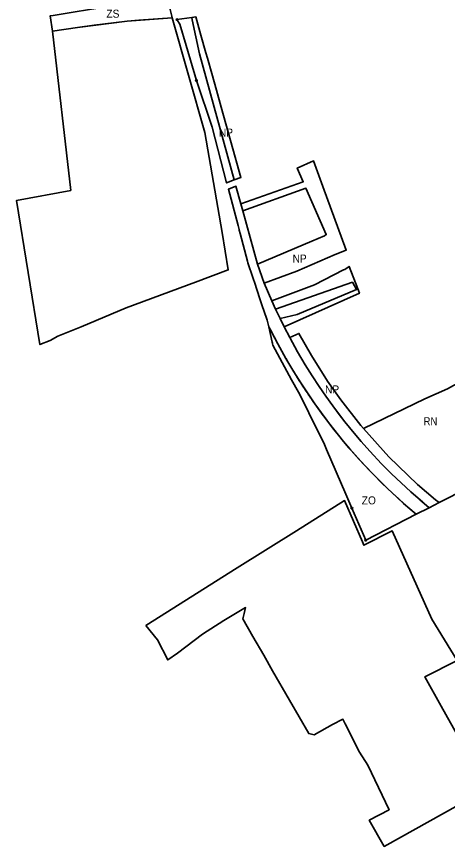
# Model space of a CAD drawing. Extents: x -650276 to -642489, y -1074311 to -1066658.
# Drawn here: x -649386 to -648741, y -1071627 to -1070383 of the extents above; entities that cross this region are included whole.
import ezdxf

# ---------------------------------------------------------------- set-up
doc = ezdxf.new("R2010")
doc.units = 0
doc.header["$LTSCALE"] = 4.8
doc.header["$PDMODE"] = 32
doc.header["$PDSIZE"] = 2.4
for name, color, linetype, lineweight in [('2', 7, 'Continuous', 35), ('24', 7, 'Continuous', 35), ('41', 7, 'Continuous', 35), ('42', 7, 'Continuous', 35), ('48', 7, 'Continuous', 35), ('7', 7, 'Continuous', 35)]:
    doc.layers.add(name, color=color, linetype=linetype, lineweight=lineweight)
doc.layers.add('62', color=7, linetype='Continuous')

msp = doc.modelspace()

# ---------------------------------------------------------------- linework, layer by layer
at = {"layer": '2'}
for points in [[(-649332.2, -1070405.42), (-649294.79, -1070399.65), (-649220.16, -1070390.26), (-649153.11, -1070385.21), (-649104, -1070557), (-649078, -1070707), (-649069, -1070763), (-649118.07, -1070781.42), (-649221.94, -1070820.12), (-649289.37, -1070848.48), (-649324.21, -1070862.51), (-649335.72, -1070868.73), (-649351, -1070875), (-649386, -1070659), (-649305, -1070644)], [(-649192.568, -1071295.954), (-649055.64, -1071209.682), (-648966.9, -1071154.34), (-648894.684, -1071108.668), (-648867.88, -1071170.58), (-648865.61, -1071175.825), (-648823.531, -1071154.018), (-648764.17, -1071286.65), (-648725.85, -1071348.28), (-648774.371, -1071372.773), (-648749.854, -1071416.727), (-648680.709, -1071540.691), (-648835.095, -1071627.059), (-648857.66, -1071587.83), (-648827.998, -1071572.04), (-648859.97, -1071505.55), (-648872.28, -1071485.58), (-648893.65, -1071443.47), (-648897.169, -1071436.535), (-648912.69, -1071444.48), (-648940.23, -1071459.65), (-648948.27, -1071457.92), (-648976.99, -1071408.03), (-649002.42, -1071363.86), (-649015.83, -1071340.58), (-649031.91, -1071312.65), (-649047.3, -1071285.92), (-649045.19, -1071277.86), (-649042.927, -1071269.216), (-649075.6, -1071288.29), (-649107.36, -1071308.9), (-649144.99, -1071337.61), (-649159.64, -1071347.68), (-649175.1, -1071317.29)]]:
    msp.add_lwpolyline(points, close=True, dxfattribs=at)
at = {"layer": '24'}
for points in [[(-649059.951, -1070628.223), (-649112.14, -1070439.152), (-649123.138, -1070388.16), (-649123.385, -1070384.775), (-649145.73, -1070387.91)], [(-649145.73, -1070387.91), (-649141.48, -1070394.84), (-649132.07, -1070426.81), (-649116.56, -1070479.19)], [(-649116.56, -1070479.19), (-649093.2, -1070549.1), (-649071.33, -1070632.6), (-649059.951, -1070628.223)]]:
    msp.add_lwpolyline(points, dxfattribs=at)
msp.add_lwpolyline([(-648976.834, -1070864.527), (-648985.145, -1070848.538), (-648991.386, -1070835.954), (-648998.132, -1070821.723), (-649003.641, -1070809.566), (-649014.888, -1070782.994), (-649025.129, -1070754.377), (-649047.11, -1070674.743), (-649050.081, -1070663.981), (-649057.338, -1070637.689), (-649068.65, -1070642.23), (-649068.65, -1070642.23), (-649054.31, -1070696.44), (-649052.77, -1070702.25), (-649052.44, -1070703.48), (-649051.03, -1070708.74), (-649040.03, -1070750.06), (-649039.38, -1070752.51), (-649039.06, -1070753.72), (-649038.51, -1070755.38), (-649027.74, -1070787.51), (-649027.64, -1070787.8), (-649019.48, -1070812.18), (-649018.48, -1070815.18), (-649011.24, -1070836.79), (-649010.67, -1070838.5), (-649007.885, -1070848.153), (-648994.464, -1070873.974), (-648982.467, -1070895.704), (-648970.712, -1070915.663), (-648960.268, -1070932.429), (-648949.389, -1070949.031), (-648939.232, -1070963.818), (-648918.601, -1070991.969), (-648896.068, -1071020.184), (-648886.874, -1071031.044), (-648874.793, -1071044.773), (-648863.847, -1071056.723), (-648851.175, -1071069.886), (-648838.696, -1071082.562), (-648823.087, -1071097.562), (-648816.379, -1071103.782), (-648806.239, -1071112.938), (-648797, -1071121), (-648790.23, -1071126.818), (-648787.207, -1071129.363), (-648767.824, -1071119.455), (-648771.725, -1071116.233), (-648781.806, -1071107.721), (-648795.407, -1071095.8), (-648824.292, -1071068.677), (-648839.273, -1071053.556), (-648856.883, -1071034.761), (-648869.629, -1071020.411), (-648880.44, -1071007.703), (-648894.164, -1070990.806), (-648902.714, -1070979.812), (-648912.396, -1070966.893), (-648922.92, -1070952.242), (-648932.78, -1070937.887), (-648943.414, -1070921.659), (-648953.605, -1070905.299), (-648965.093, -1070885.794)], close=True, dxfattribs=at)
for p in [(-649145.73, -1070387.91), (-649116.56, -1070479.19)]:
    msp.add_point(p, dxfattribs=at)
at = {"layer": '41'}
msp.add_lwpolyline([(-649159.19, -1070358.82), (-649197.91, -1070361.8), (-649203.4, -1070362.23), (-649220.47, -1070363.94), (-649231.39, -1070365.69), (-649273.57, -1070372.44), (-649304.18, -1070377.35), (-649331.3, -1070381.69), (-649335.79, -1070382.41), (-649332.2, -1070405.42), (-649294.79, -1070399.65), (-649269.769, -1070396.502), (-649220.16, -1070390.26), (-649202.969, -1070388.965), (-649153.11, -1070385.21), (-649153.64, -1070382.9)], close=True, dxfattribs=at)
at = {"layer": '42'}
for p, q in [((-648883.73, -1071120.13), (-648862.97, -1071168.09)), ((-648862.97, -1071168.09), (-648787.207, -1071129.363))]:
    msp.add_line(p, q, dxfattribs=at)
for points in [[(-649002.97, -1070857.609), (-649007.885, -1070848.153), (-649003.1, -1070871.35), (-649002.82, -1070872.69), (-649002.62, -1070873.69), (-649002.15, -1070875.96), (-648974.4, -1070927.77), (-648963.5, -1070946.45), (-648959.92, -1070953.73), (-648948.29, -1070977.37), (-648924.92, -1071024.89), (-648922.98, -1071029.49), (-648921.87, -1071032.04), (-648892.82, -1071099.15), (-648883.73, -1071120.13)], [(-648994.42, -1070874.053), (-648994.464, -1070873.974), (-648994.52, -1070873.867)], [(-648982.403, -1070895.812), (-648982.467, -1070895.704), (-648982.524, -1070895.601)], [(-648970.64, -1070915.778), (-648970.712, -1070915.663), (-648970.771, -1070915.564)], [(-648960.194, -1070932.542), (-648960.268, -1070932.429), (-648960.34, -1070932.313)], [(-648949.345, -1070949.096), (-648949.389, -1070949.031), (-648949.428, -1070948.972)], [(-648939.179, -1070963.89), (-648939.232, -1070963.818), (-648939.33, -1070963.675)], [(-648918.464, -1070992.141), (-648918.601, -1070991.969), (-648918.737, -1070991.784)]]:
    msp.add_lwpolyline(points, dxfattribs=at)
for start, end in [(206.85611, 208.07207), (208.08607, 209.71957), (209.73567, 211.25686), (211.27351, 212.56631), (212.58435, 213.8879), (213.89777, 215.07157), (215.08899, 217.38409), (217.41391, 230.04071)]:
    msp.add_arc((-648232.695, -1070467.567), 863.398, start, end, dxfattribs=at)
for p in [(-648883.73, -1071120.13), (-648862.97, -1071168.09)]:
    msp.add_point(p, dxfattribs=at)
at = {"layer": '48'}
msp.add_line((-648894.164, -1070990.806), (-648880.44, -1071007.703), dxfattribs=at)
for points in [[(-649059.951, -1070628.223), (-649049.96, -1070624.38), (-649055.93, -1070603.08), (-649058.38, -1070594.33), (-649065.42, -1070569.21), (-649072.47, -1070544.09), (-649079.51, -1070518.97), (-649086.55, -1070493.85), (-649093.59, -1070468.73), (-649100.01, -1070445.82), (-649102.31, -1070437.61), (-649109.76, -1070411.05), (-649117.36, -1070383.93), (-649123.385, -1070384.775), (-649123.138, -1070388.16), (-649112.14, -1070439.152)], [(-649014.888, -1070782.994), (-648966.35, -1070764.7), (-648908.94, -1070740.19), (-648892.215, -1070733.293), (-648927.2, -1070637.98), (-648941.064, -1070599.735), (-648965.569, -1070610.382), (-648956.687, -1070630.825), (-649050.081, -1070663.981), (-649047.11, -1070674.743), (-648952.455, -1070640.564), (-648922.196, -1070710.207), (-648924.668, -1070712.022), (-648943.837, -1070720.104), (-649025.129, -1070754.377)], [(-648985.145, -1070848.538), (-648872.375, -1070798.112), (-648874.87, -1070791.61), (-648887.84, -1070757.84), (-648894.08, -1070762.22), (-648896.11, -1070762.73), (-648939.5, -1070785.4), (-649003.641, -1070809.566), (-648998.132, -1070821.723), (-648882.919, -1070781.673), (-648876.64, -1070792.6), (-648965.475, -1070829.829), (-648991.386, -1070835.954)]]:
    msp.add_lwpolyline(points, close=True, dxfattribs=at)
for points in [[(-648866.341, -1071000.881), (-648870.479, -1070996.265), (-648900.337, -1070957.964), (-648920.293, -1070929.567), (-648944.376, -1070891.404), (-648963.107, -1070858.328), (-648976.834, -1070864.527)], [(-648976.834, -1070864.527), (-648965.093, -1070885.794), (-648953.605, -1070905.299), (-648943.414, -1070921.659), (-648932.78, -1070937.887), (-648922.92, -1070952.242), (-648912.396, -1070966.893), (-648894.164, -1070990.806)], [(-648880.44, -1071007.703), (-648869.629, -1071020.411), (-648856.883, -1071034.761), (-648839.273, -1071053.556), (-648824.292, -1071068.677), (-648795.407, -1071095.8), (-648777.641, -1071111.238), (-648771.725, -1071116.233), (-648767.824, -1071119.455), (-648752.967, -1071111.861), (-648758.423, -1071107.756), (-648785.386, -1071084.634), (-648828.353, -1071043.265), (-648866.341, -1071000.881)]]:
    msp.add_lwpolyline(points, dxfattribs=at)
at = {"layer": '7'}
msp.add_lwpolyline([(-648866.341, -1071000.881), (-648828.353, -1071043.265), (-648785.386, -1071084.634), (-648758.423, -1071107.756), (-648752.967, -1071111.861), (-648734.849, -1071102.599), (-648651.375, -1071057.109), (-648627.39, -1071042.65), (-648655.76, -1070997.5), (-648634.07, -1070983.17), (-648571.14, -1070944.67), (-648540.7, -1070928.6), (-648479.18, -1070891.26), (-648386.587, -1070833.807), (-648427.25, -1070767.95), (-648511.09, -1070814.7), (-648721.54, -1070930.88), (-648740.25, -1070941.21), (-648774.23, -1070956.42)], close=True, dxfattribs=at)

# ---------------------------------------------------------------- texts
at = {"layer": '62'}
for s, width, p in [('ZS', 0.95, (-649251.482, -1070385.05)), ('NP', 0.95, (-649082.942, -1070563.157)), ('NP', 0.95, (-648972.583, -1070752.041)), ('NP', 0.95, (-648923.942, -1070948.157)), ('RN', 0.9, (-648776.428, -1070995.883)), ('ZO', 0.95, (-648868.886, -1071114.486))]:
    msp.add_text(s, height=12, dxfattribs=dict(at, width=width)).set_placement(p)

doc.saveas('drawing.dxf')
